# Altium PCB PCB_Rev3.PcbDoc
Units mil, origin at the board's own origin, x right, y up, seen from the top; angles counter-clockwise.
Board outline 2029.05 x 1535 mil, 2 copper layers (Top Layer, Bottom Layer), stack 61.2 mil thick; 19 components, 17 nets, 98 pads, 17 vias.
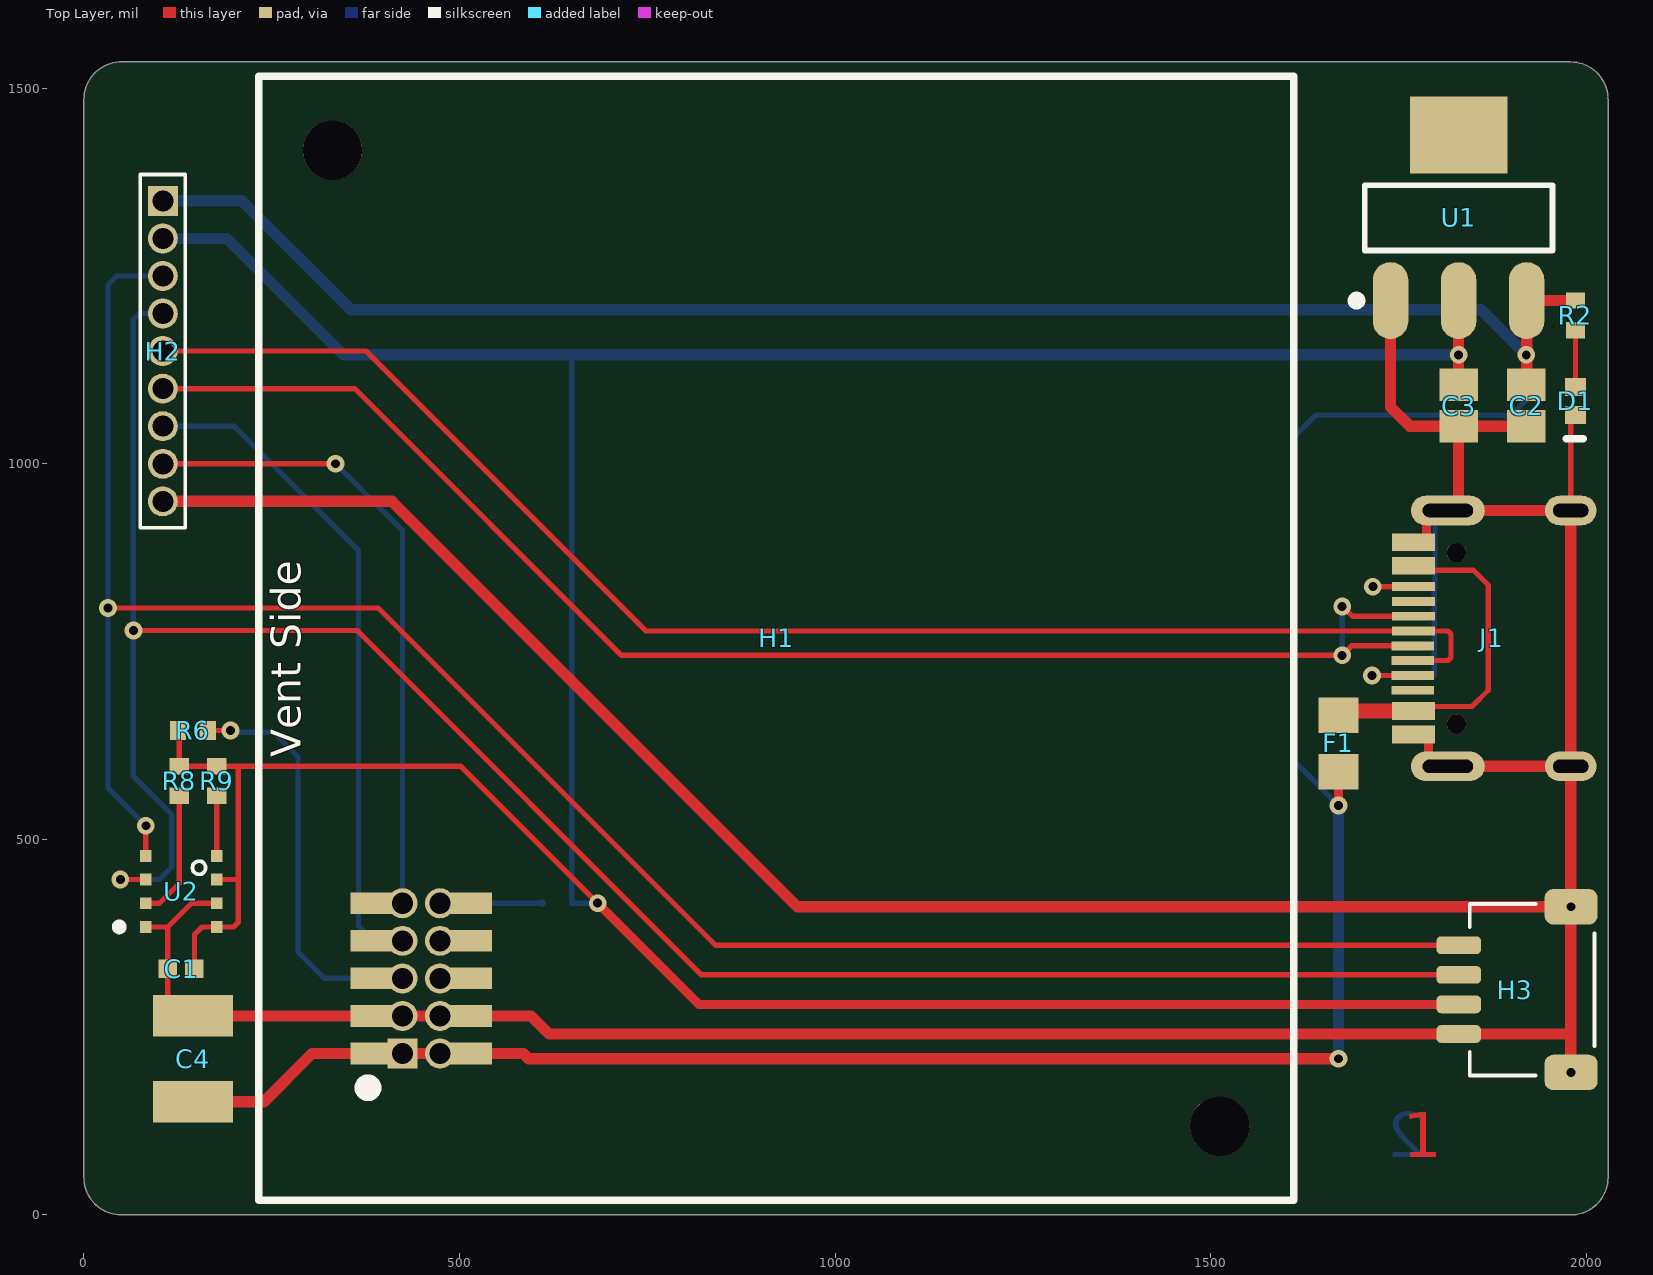
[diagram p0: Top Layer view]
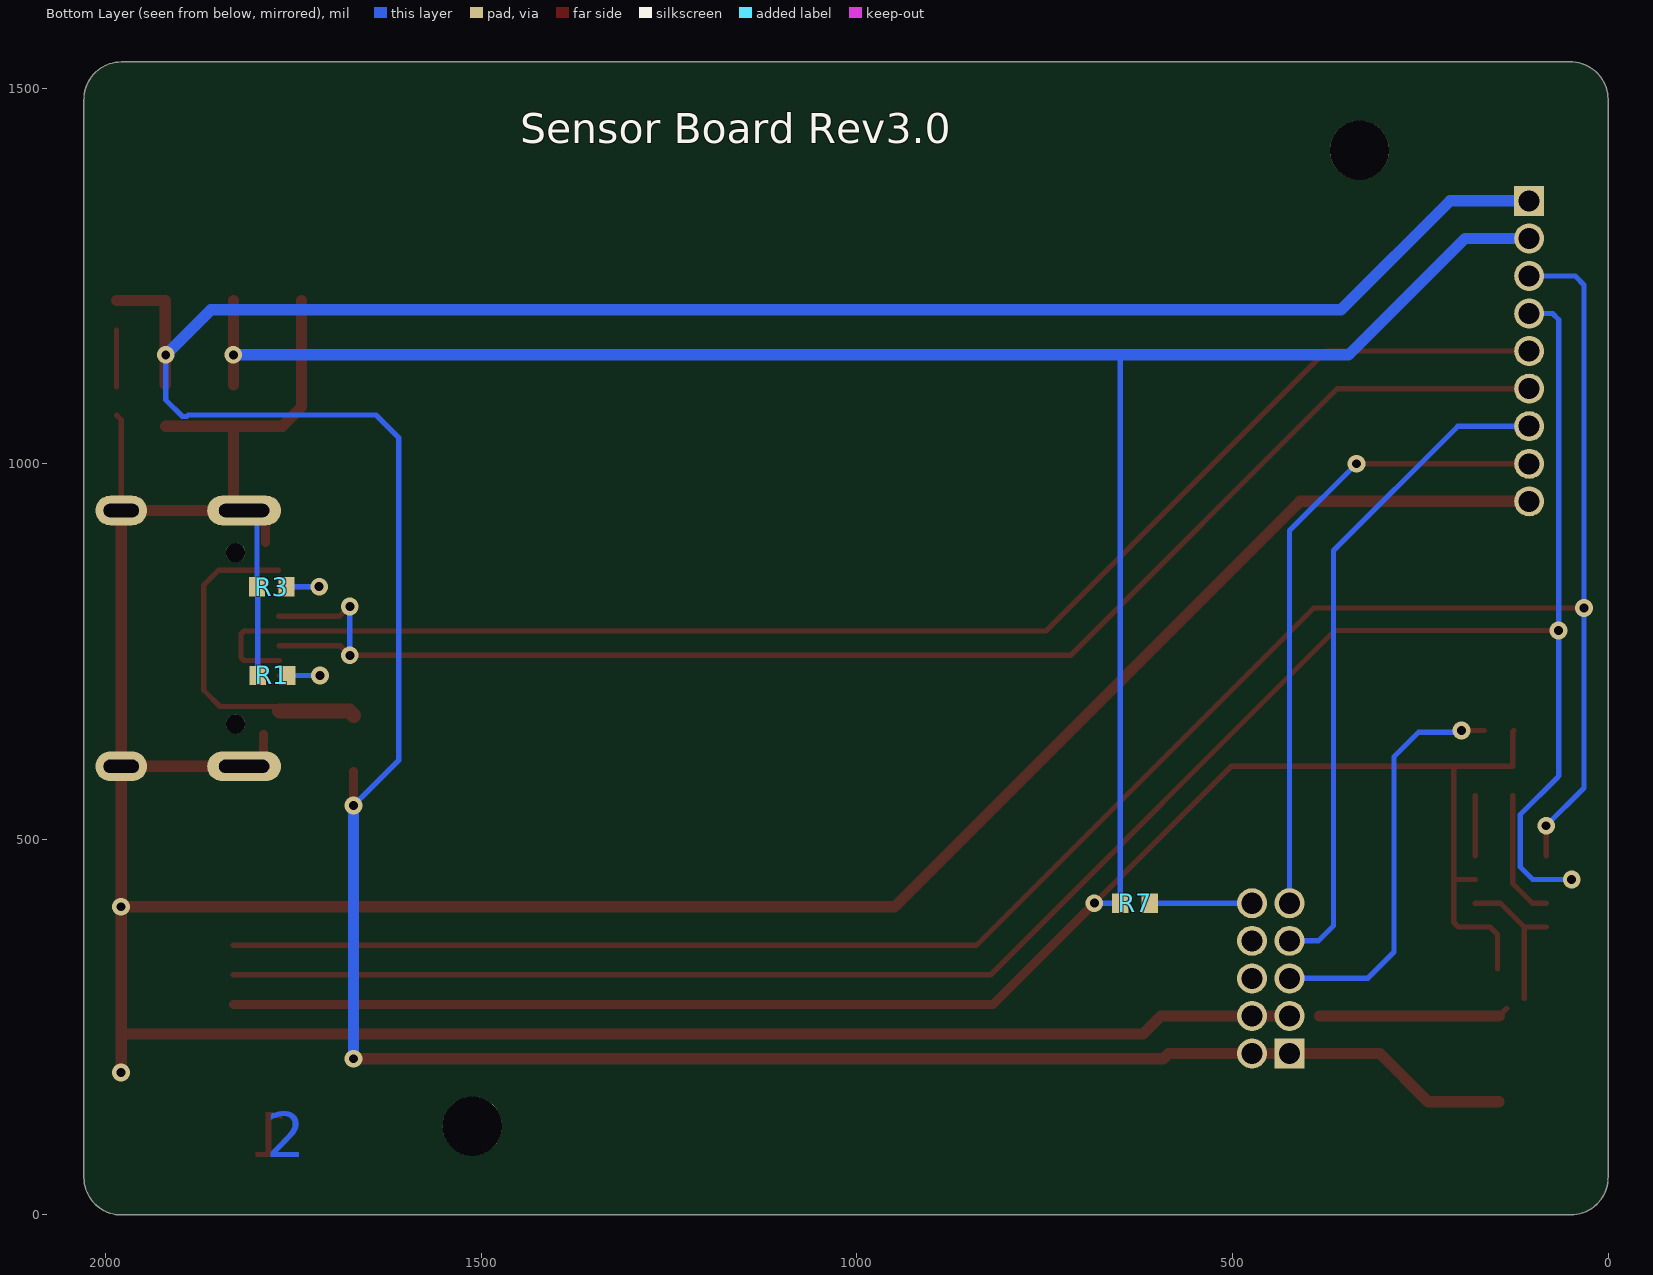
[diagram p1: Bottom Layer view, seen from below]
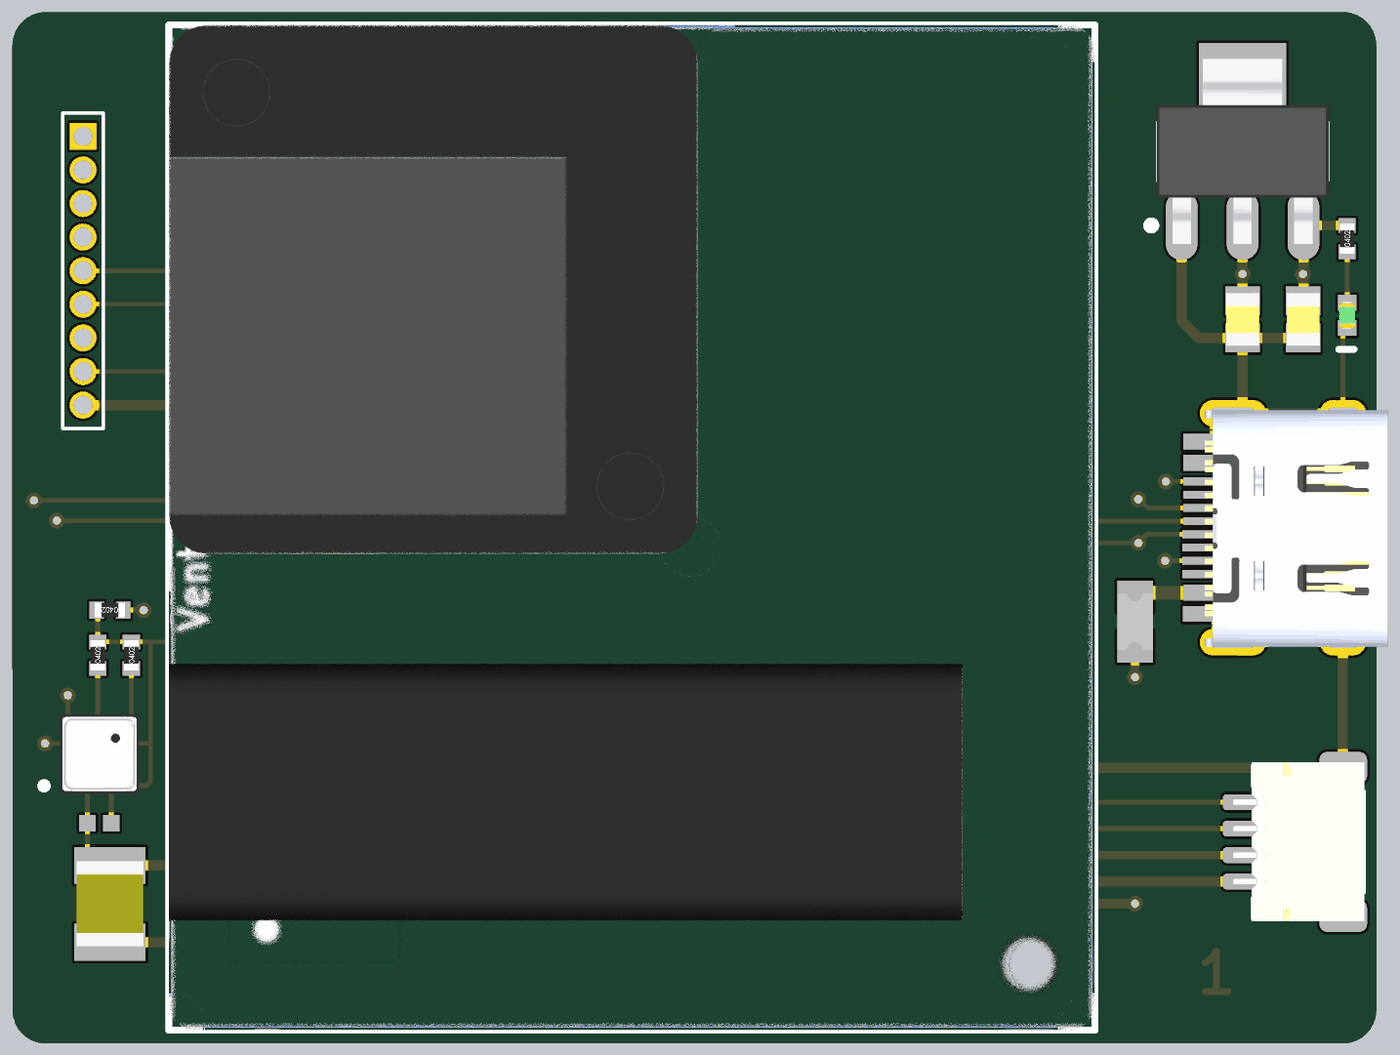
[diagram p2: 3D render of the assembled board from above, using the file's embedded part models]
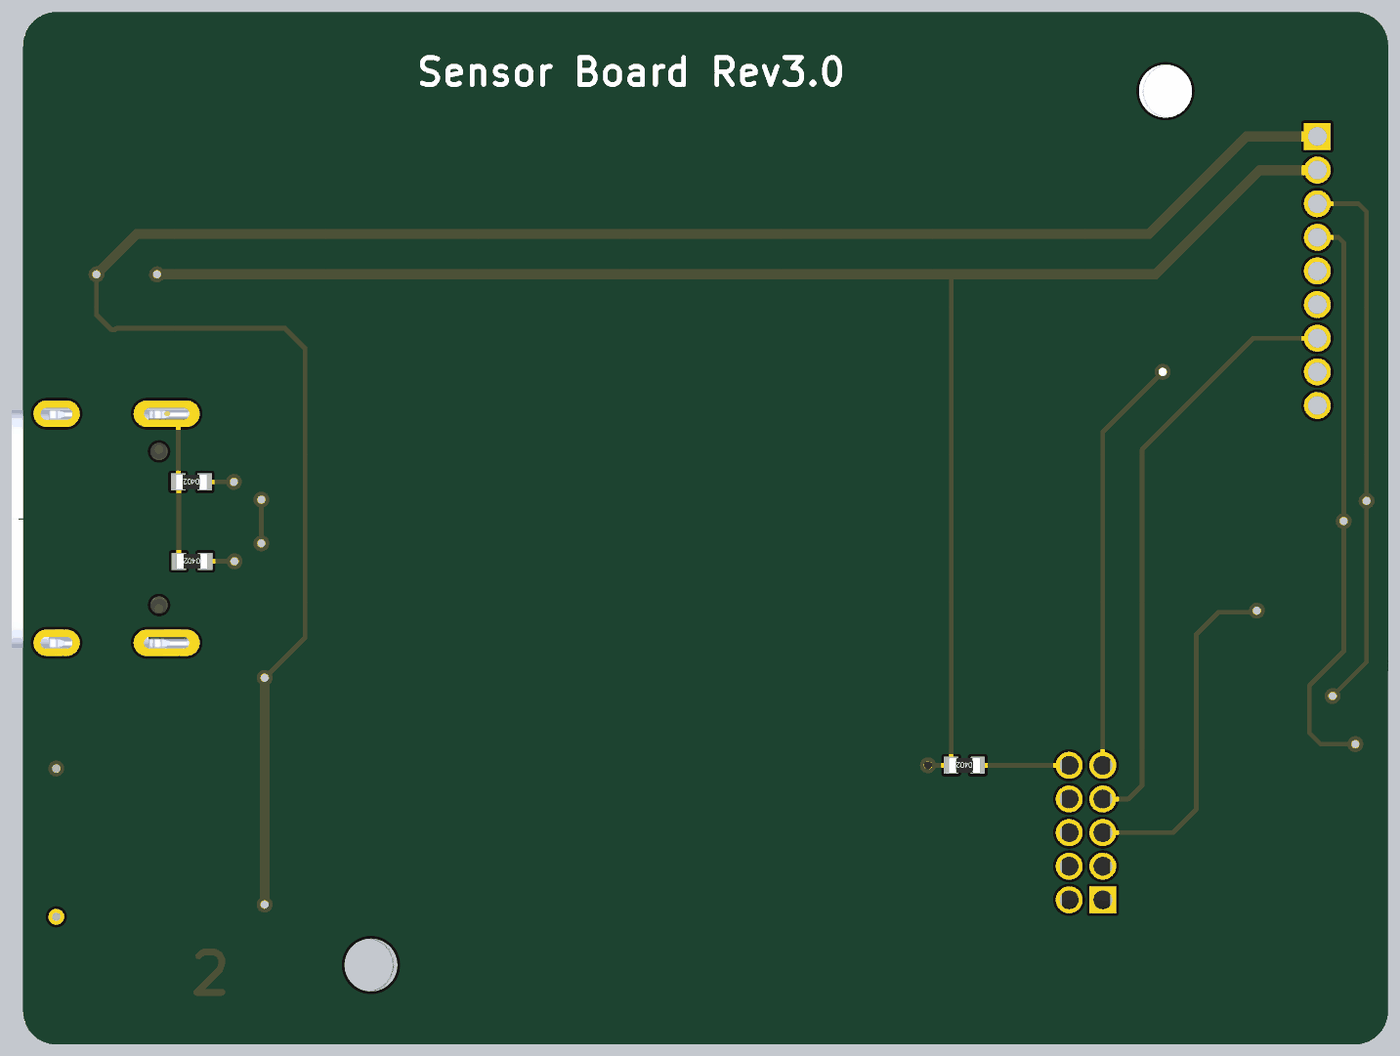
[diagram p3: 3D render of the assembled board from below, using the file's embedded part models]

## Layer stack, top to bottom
Top Solder: solder mask 0.4, Solder Resist, Dk 3.5
Top Layer: signal copper 1.4
Dielectric 1: dielectric 58.4, FR-4, Dk 4.8
Bottom Layer: signal copper 1.4
Bottom Solder: solder mask 0.4, Solder Resist, Dk 3.5

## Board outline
0,51.04 ccw(c49.99,50) 49.99,0 1977.95,0 1977.95,0.01 ccw(c1978.99,50) 2028.99,50 2028.99,1483.96 2028.92,1483.96 ccw(c1978.94,1485) 1978.94,1535 50.98,1535 50.98,1534.99 ccw(c49.94,1485) -0.06,1485

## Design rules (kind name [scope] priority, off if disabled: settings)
Clearance Clearance_J1 [All vs InComponent('J1')] p1: gap=7 ignorepadtopadclearanceinfootprint=FALSE
Clearance Clearance_U2 [All vs InComponent('U2')] p2: gap=5 ignorepadtopadclearanceinfootprint=FALSE
Clearance [All] p3: gap=10 ignorepadtopadclearanceinfootprint=FALSE except(0: Arc-Hole Track-Hole SMDPad-Hole THPad-Hole Via-Hole Fill-Hole Poly-Hole Region-Hole Text-Hole)
MinimumSolderMaskSliver [All] p1: minsoldermaskwidth=2
PolygonConnect [All] p1: connectstyle=Relief reliefconductorwidth=10 reliefentries=4 polygonreliefangle="90 Angle" airgapwidth=10
RoutingVias [All] p1: holewidth=28 width=50 viastyle="Through Hole" minholewidth=28 minwidth=50 maxholewidth=28 maxwidth=50
SilkToSilkClearance [All] p1: silktosilkclearance=5
SilkToSolderMaskClearance [IsPad] p1: minsilkscreentomaskgap=5 clearancetoexposedcopper=TRUE
SolderMaskExpansion [All] p1: expansion=4 istentingtop=FALSE
Width [All] p1: maxlimit=20 minlimit=7 preferedwidth=7
27 further rules are at their usual default settings.

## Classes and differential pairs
component class Schematic_Rev3: C1 C2 C3 C4 D1 F1 H1 H2 H3 J1 R1 R2 R3 R7 R8 R9 U1 U2

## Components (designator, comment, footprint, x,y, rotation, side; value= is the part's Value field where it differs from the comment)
C1 "0.1uF" CAPC1005X56N 129.34,327.73 r180 top
C2 "10uF" CAPC2012X140N 1919.94,1077.54 r270 top
C3 "10uF" CAPC2012X140N 1829.94,1077.54 r270 top
C4 "47uF" CAPC3225X160N 145,207.91 r90 top
D1 "Green Led" LED1005X40N-Green 1985.52,1083.56 r90 top
F1 "TLC-PSMD050" PTC2012X70L 1669.94,627.7 r90 top
H1 "PMSA003-A" PMSA003-A 1610.4,19.72 r0 top locked
H2 "CON9" HDR9X1-50MIL 105,950 r0 top
H3 "QWiiC" SM04B-SRSS-TB 1904.94,300 r90 top
J1 "USB-C" TYPE-C-31-M-12 1971.39,937.78 r90 top locked
R1 "5.1K" "RESC1005X40L (0402 FOOTPRINT)" 1777.91,718.29 r0 bottom
R2 "22K" "RESC1005X40L (0402 FOOTPRINT)" 1985.52,1197.58 r90 top
R3 "5.1K" "RESC1005X40L (0402 FOOTPRINT)" 1778.89,836.4 r0 bottom
R6 "10K" "RESC1005X40L (0402 FOOTPRINT)" 145,645 r180 top
R7 "10K" "RESC1005X40L (0402 FOOTPRINT)" 629.62,415.1 r0 bottom
R8 "10K" "RESC1005X40L (0402 FOOTPRINT)" 126.88,577.8 r90 top
R9 "10K" "RESC1005X40L (0402 FOOTPRINT)" 176.88,577.8 r90 top
U1 "NCP1117LPST33T3G" SOT230P700X180-4N 1829.97,1327.5 r270 top value="3.3V 1A LDO"
U2 "BME680" LGA3X3-8N 129.64,430.75 r180 top

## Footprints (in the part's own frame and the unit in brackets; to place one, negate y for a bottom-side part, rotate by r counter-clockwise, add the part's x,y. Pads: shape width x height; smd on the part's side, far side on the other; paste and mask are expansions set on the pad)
CAPC1005X56N [mm] "Chip Capacitor, 2-Leads, Body 1.0x0.5mm, IPC Medium Density (0402 ceramic)"
  rect 0.62x0.62 smd: 1(-0.45,0) 2(0.45,0)
  body extent -0.55,-0.3 0.55,0.3, height 0.6
CAPC2012X140N [mm] "Chip Capacitor, 2-Leads, Body 2.0x1.3mm, IPC Medium Density (0805 ceramic)"
  rect 1.1x1.3 smd: 1(-0.7,0) 2(0.7,0)
  body extent -1,-0.62 1,0.63, height 1.24
CAPC3225X160N [mm] "Chip Capacitor, 2-Leads, Body 3.2x2.5mm, IPC Medium Density, (1210)"
  rect 1.4x2.7 smd: 1(-1.45,0) 2(1.45,0)
  body extent -1.61,-1.26 1.61,1.26, height 0.62
HDR9X1-50MIL [mil]
  rect 40x40 hole 28: 1(0,400)
  round 40 hole 28: 2(0,350) 3(0,300) 4(0,250) 5(0,200) 6(0,150) 7(0,100) 8(0,50) 9(0,0)
  silkscreen extent -30,-35 30,435
LED1005X40N-Green [mm] "Chip LED 2-Leads, Body 1.0x0.5mm, (0402)"
  rect 0.6x0.7 smd: 1(-0.475,0) 2(0.475,0)
  body extent -0.5,-0.3 0.5,0.3, height 0.2
LGA3X3-8N [mm] "LGA 3X3"
  rect 0.4x0.4 smd mask+0.076: 1(1.2,1.2) 2(1.2,0.4) 5(-1.2,-1.2) 6(-1.2,-0.4) 7(-1.2,0.4) 8(-1.2,1.2)
  rect 0.4x0.4 smd paste+0 mask+0.076: 3(1.2,-0.4) 4(1.2,-1.2)
  silkscreen extent -0.82,-1.02 2.22,1.32, body extent -1.5,-1.5 1.5,1.5, height 1.01
PMSA003-A [mil] "Air Quality Sensor"
  rect 58x29 smd: 1(-1226.41,195.28) 2(-1096.41,195.28) 3(-1226.41,245.28) 4(-1096.41,245.28) 5(-1226.41,295.28) 6(-1096.41,295.28) 7(-1226.41,345.28) 8(-1096.41,345.28) 9(-1226.41,395.28) 10(-1096.41,395.28)
  rect 40x40 hole 28: 1(-1186.42,195.28)
  round 40 hole 28: 2(-1136.42,195.28) 3(-1186.42,245.28) 4(-1136.42,245.28) 5(-1186.42,295.28) 6(-1136.42,295.28) 7(-1186.42,345.28) 8(-1136.42,345.28) 9(-1186.42,395.28) 10(-1136.42,395.28)
  round 0 all layers, no hole: 7(-1136.42,345.28)
  round 78.74 hole 78.74 unplated: ""(-1279.53,1397.64) ""(-98.43,98.43)
  silkscreen extent -1378,0 0,1496, body extent -1378,0 0,1496, height 480
PTC2012X70L [mm] "Chip Fuse, 2-Leads, Body 2.0x1.3mm, IPC Medium Density (0805)"
  rect 1.2x1.35 smd: 1(-0.95,0) 2(0.95,0)
  body extent -1.07,-0.67 1.08,0.68, height 0.66
"RESC1005X40L (0402 FOOTPRINT)" [mm] "Chip Resistor, 2-Leads, Body 1.0x0.5mm, IPC Medium Density (0402)"
  rect 0.55x0.65 smd: 1(-0.5,0) 2(0.5,0)
  body extent -0.57,-0.27 0.58,0.28, height 0.41
SM04B-SRSS-TB [mm] "CONN HEADER 4POS .100 R/A QWIIC"
  rrect50% 0.6x1.5 smd: 1(1.5,1.9) 2(0.5,1.9) 3(-0.5,1.9) 4(-1.5,1.9)
  rrect50% 1.2x1.8 smd: 5(-2.8,-1.9) 5(2.8,-1.9)
  silkscreen extent -2.9,-2.69 2.9,1.52, body extent -3,-2.69 3,2.26, height 3.25
SOT230P700X180-4N [mm] "SOT223, 4-Leads, Body 6.7x7.3mm (max), Pitch 2.30mm, IPC Medium Density"
  oval 2.6x1.2 smd: 1(2.8,-2.3) 2(2.8,0) 3(2.8,2.3)
  rect 2.6x3.3 smd: 4(-2.8,0)
  silkscreen extent -1.1,-3.57 2.92,3.18, body extent -3.5,-3.25 3.5,3.25, height 1.65
TYPE-C-31-M-12 [mm] "USB-C Connector"
  oval 1x1.75 hole 0.45 slot 1.2 at 90 deg: 1(-8.65,-0.2) 1(0,-0.2)
  oval 1x2.5 hole 0.45 slot 1.7 at 90 deg: 1(-8.65,3.955) 1(0,3.955)
  rect 0.3x1.45 smd: A1(-7.726,5.119) A4(-6.926,5.117) A5(-5.575,5.142) A6(-4.575,5.142) A7(-4.075,5.117) A8(-3.075,5.117) A9(-1.727,5.117) A12(-0.924,5.117) B1(-1.224,5.117) B4(-2.021,5.117) B5(-2.575,5.117) B6(-3.575,5.117) B7(-5.075,5.142) B8(-6.075,5.142) B9(-6.626,5.117) B12(-7.426,5.119)
  round 0.65 hole 0.65 unplated: ""(-7.225,3.667) ""(-1.425,3.667)
  body extent -8.82,-1.89 0.12,5.01, height 3.31

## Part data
C1: library part CAP_0402, "CAP 0.1uF 0402"
C2 C3: library part CAP_0805, "CAP 10uF 16V 0805", Manufacturer=Murata, PartNumber=C162317
C4: library part CAP_1210, "CAP 47uF 1210"
D1: library part LED_0402_SMALL_GREEN, "LED Green 0402", PartNumber=C74338
F1: library part PTC_FUSE, "PTC FUSE 500mA hold, 1A trip 0805 SMD", LCSC_Part_Number=C261942, Manufacturer=TLC
H1: "Dust Particle Sensor I2C", Manufacturer=Plantower, PartNumber=C132744
H2: "CONN HEADER 9POS .100\" PADS", PartNumber=PADS
H3: library part SM04B-SRSS-TB, "CONN HEADER 4POS .100 R/A QWIIC", LCSC_Part_Number=C160404, Manufacturer=JST, PartNumber=SM04B-SRSS-TB(LF)(SN)
J1: "CONN RECPT USB-C", Manufacturer=KHE, PartNumber=C165948
R1 R3: library part RES_0603, "RES 5.1K 0402"
R2: library part RES_0603, "RES 22K 0402", Manufacturer="LIZ Elec", PartNumber=C100310
R6 R7 R8 R9: library part RES_0603, "RES 10K 0402", Manufacturer="LIZ Elec", PartNumber=C100310
U1: "IC REG LDO 3.3V 1A SOT223-3", Manufacturer="ON Semi"
U2: "Gas, Humidity, Pressure, Temperature Sensor I2C,", Manufacturer=Bosch

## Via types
v1: diameter 23.62, hole 11.81, Top Layer to Bottom Layer, tented both sides, 16 vias
v2: diameter 23.62, hole 11.81, Top Layer to Bottom Layer, 1 vias

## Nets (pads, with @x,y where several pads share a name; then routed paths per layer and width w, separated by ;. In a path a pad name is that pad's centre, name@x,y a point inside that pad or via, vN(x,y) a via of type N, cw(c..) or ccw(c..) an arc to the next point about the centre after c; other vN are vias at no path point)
+3.3V: C1.1 C3.1 H2.2 H3.3 R6.2 R7.2 R8.2 R9.2 U1.2 U2.6 U2.8 | length 4894.5
  Top Layer w7: R6.2 126.88,643.43 R8.2 R9.2 205.57,597.49 ; C1.1 147.05,373.16 157.4,383.5 U2.8 199.07,383.5 205.57,390 205.57,445 ; U2.6 205.57,446.5 205.57,597.49 ; v1(683.87,415.1) 501.48,597.49 205.57,597.49 ; C3.1 C3.1@1829.97,1105.14
  Top Layer w12: v1(683.87,415.1) 818.65,280.32 H3.3
  Top Layer w15: C3.1@1829.97,1105.14 U1.2
  Bottom Layer w7: 650,1145 649.31,1144.31 R7.2 v1(683.87,415.1)
  Bottom Layer w15: H2.2 190.57,1300 345.57,1145 650,1145 v1(1830,1145)
+5V: C2.1 C4.1 F1.1 H1.1 H1.2 H2.1 R2.2 U1.3 | length 4922.8
  Top Layer w7: C4.1@145.1,150.73 C4.1@146.08,149.74 ; v1(1669.94,545.06) v1@1670,545 ; C2.1 C2.1@1920.52,1105.69
  Top Layer w12: v1(1669.94,545.06) F1.1
  Top Layer w15: C4.1@145.1,150.73 239.5,150.73 303.77,215 423.98,215 473.98,215 513.99,215 585,215 592,208 v1(1670,208) ; C2.1@1920.52,1105.69 U1.3 R2.2
  Bottom Layer w7: v1(1669.94,545.06) 1610,605 1610,1035 1640,1065 1890,1065 1892.1,1062.9 1897.9,1062.9 1920,1085 v1(1920,1145)
  Bottom Layer w15: H2.1 210.57,1350 355.57,1205 1860,1205 v1(1920,1145) ; v1(1669.94,545.06) 1669.94,208.07 v1(1670,208)
D+: H2.6 J1.A6 J1.B6 | length 1981.6
  Top Layer w7: H2.6 360.57,1100 715.57,745 v1(1674.94,745) 1687.59,757.66 J1.A6 ; v1(1674.94,810) 1675.61,810 1688.58,797.03 J1.B6
  Bottom Layer w7: v1(1674.94,745) v1(1674.94,810)
D-: H2.5 J1.A7 J1.B7 | length 1954.8
  Top Layer w7: H2.5 375.57,1150 748.22,777.34 J1.A7 1815.84,777.34 1819.94,773.24 1819.94,742.07 1815.84,737.97 J1.B7
GND: C1.2 C2.2 C3.2 C4.2 D1.1 H1.3 H1.4 H2.9 H3.4 H3.5 J1.1 J1.A1 J1.A12 J1.B1 J1.B12 R1.2 R3.2 U1.1 U2.1 U2.7 | length 6071.3
  Top Layer w7: U2.1 111.62,383.5 ; C4.2@111.62,288.5 C1.2 111.62,383.5 ; C4.2@135,275 C4.2 ; U2.7 143.12,415 111.62,383.5 ; J1.1@1815.68,937.78 1827.78,937.78 J1.1@1829.94,939.94 ; 1975.21,240.95 1979.26,245 ; H3.5@1979.26,190.24 v2(1979.74,189.76) ; H3.5@1979.26,410.24 v1(1979.74,410.24) ; J1.1@1979.26,937.78 1979.26,1058.6 D1.1
  Top Layer w12: J1.B1@1787.17,895.19 J1.1@1787.17,937.19 ; J1.1@1790.17,598.19 J1.B12@1790.17,639.5
  Top Layer w15: H2.9 410,950 949.76,410.24 H3.5@1979.26,410.24 ; C4.2 H1.3@383.99,265 ; H1.3@423.98,265 473.98,265 595,265 619.06,240.95 H3.4 1975.21,240.95 ; U1.1 1739.42,1075.58 1765.02,1049.98 C3.2 ; J1.1@1827.78,597.22 J1.1@1979.26,597.22 ; J1.1@1827.78,937.78 1979.26,937.78 J1.1@1979.26,597.22 ; J1.1@1829.94,939.94 C3.2 ; C2.2 C3.2 ; H3.5@1979.26,190.24 1979.26,245 H3.5@1979.26,410.24 ; H3.5@1979.26,410.24 J1.1@1979.26,597.22
  Bottom Layer w7: R1.2 1797.59,835.41 R3.2 1798.58,922.82 1813.53,937.78 J1.1@1815.68,937.78
NetD1_2: D1.2 R2.1 | length 75.6
  Top Layer w7: D1.2 R2.1
NetF1_2: F1.2 J1.A4 J1.A9 J1.B4 J1.B9 | length 456.9
  Top Layer w7: J1.B9 1847.68,676.9 1869.38,698.6 1869.38,838.6 1849.79,858.2 J1.B4
  Top Layer w20: F1.2 1675.45,670.61 J1.A4@1768.6,670.61
NetH1_5: H1.5 R6.1 | length 548.3
  Top Layer w7: R6.1 v1(195,645)
  Bottom Layer w7: v1(195,645) 197.31,642.69 252.31,642.69 285,610 285,350 320,315 H1.5@423.98,315
NetH1_10: H1.10 R7.1 | length 136
  Bottom Layer w7: H1.10@474.03,415.05 R7.1@609.88,415.05
  Bottom Layer w10: H1.10@473.98,415 H1.10@474.03,415.05 ; R7.1@609.88,415.05 R7.1
NetJ1_A5: J1.A5 R1.1 | length 97.5
  Top Layer w7: v1(1714.82,718.29) J1.A5
  Bottom Layer w7: v1(1714.82,718.29) R1.1
NetJ1_B5: J1.B5 R3.1 | length 97.5
  Top Layer w7: v1(1715.8,836.4) J1.B5
  Bottom Layer w7: v1(1715.8,836.4) R3.1
NetR8_1: R8.1 U2.2 | length 172.2
  Top Layer w7: U2.2 100.57,415 126.88,441.32 R8.1
NetR9_1: R9.1 U2.5 | length 80.1
  Top Layer w7: U2.5 R9.1
Rx: H1.7 H2.7 | length 895.3
  Bottom Layer w7: H2.7 200,1050 365.57,884.43 365.57,385 385.57,365 H1.7@423.98,365
SCL: H2.3 H3.1 U2.4 | length 2843.3
  Top Layer w7: v1(31.88,808.12) 391.82,808.12 840.88,359.06 H3.1 ; U2.4 v1(82.4,518.12)
  Bottom Layer w7: v1(82.4,518.12) 31.88,568.63 v1(31.88,808.12) 31.88,1238.12 43.77,1250 H2.3
SDA: H2.4 H3.2 U2.3 | length 2863.1
  Top Layer w7: v1(48.5,446.5) U2.3 ; v1(65.88,778.12) 363.82,778.12 822.25,319.69 H3.2
  Bottom Layer w7: v1(48.5,446.5) 100.26,446.5 116.88,463.12 116.88,533.12 66.88,583.12 ; 71.88,578.12 65.57,584.43 65.57,1191.8 73.77,1200 H2.4
Tx: H1.9 H2.8 | length 851.9
  Top Layer w7: H2.8 v1(335,1000)
  Bottom Layer w7: v1(335,1000) 423.98,911.02 H1.9@423.98,415
pads on no net: H1. H1.6 H1.8 J1. J1.A8 J1.B8 U1.4

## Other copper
Top Layer:
  text "1" at 1755.94,77 h60
Bottom Layer:
  text "2" at 1785.94,77 h60

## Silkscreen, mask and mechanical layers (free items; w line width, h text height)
Top Overlay:
  lines w10: 1973,1033 1996,1033
Bottom Overlay:
  text "Sensor Board Rev3.0" at 1448,1427 h40
Mechanical 1:
  lines w10: -0.06,51.04 -0.06,1485 cw(c49.94,1485) 50.98,1534.99 1978.94,1535 cw(c1978.94,1485) 2028.92,1483.96 ; 0,51.04 ccw(c49.99,50) 49.99,0 1977.95,0 ccw(c1978.99,50) 2028.99,50 2028.99,1483.96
